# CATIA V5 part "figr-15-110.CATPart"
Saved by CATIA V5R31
Part number: Part1
Bounding box of the stored display mesh (mm): x 0.737 to 206.429, y 0 to 112.04, z -1 to 2
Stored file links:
  D:\PROJECTS\Project 2021\US EDITION\CATIA V5 6R 2021\Resources\Part Files\c15_catia_v5_6r2021_prt\figr-15-110.CATPart
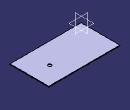
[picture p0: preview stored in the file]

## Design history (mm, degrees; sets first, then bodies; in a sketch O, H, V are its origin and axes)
SheetMetalParameters1: Thickness 2, BendRadius 4, KFactor 0.400515 {= log(min(100,max(20*SheetMetalParameters1.BendRadius,SheetMetalParameters1.Thickness)/SheetMetalParameters1.Thickness))/log(100)/2}, ReliefRadialLength 1, ReliefAxialLength 2, MinimumBendRadius 0
Body1 (main body)
  Sketch1 on xy-plane, origin (0, 0, 0), H (1, 0, 0), V (0, 1, 0)
    line L1 (0.7372, 112.0403) -> (206.4285, 112.0403)
    line L2 (206.4285, 112.0403) -> (206.4285, 0)
    line L3 (206.4285, 0) -> (0.7372, 0)
    line L4 (0.7372, 0) -> (0.7372, 112.0403)
    horizontal: L1 H, L3 H
    vertical: L2 V, L4 V
  Wall1: Thickness 2, Profile Sketch1, OffsetValue 0
  Sketch2 on face of Wall1, origin (152.409, 60.7083, 2), H (1, 0, 0), V (0, 1, 0)
    point P1 (0, 0)
  d_Stamp1: KFacteur 0.400515 {= SheetMetalParameters1.KFactor}, NewRoot_AttribNormalisation "No Standard", Stamp_FilletActivity false, Stamp_FilletRadius 2, Stamp_IntersectFilletRadius 2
